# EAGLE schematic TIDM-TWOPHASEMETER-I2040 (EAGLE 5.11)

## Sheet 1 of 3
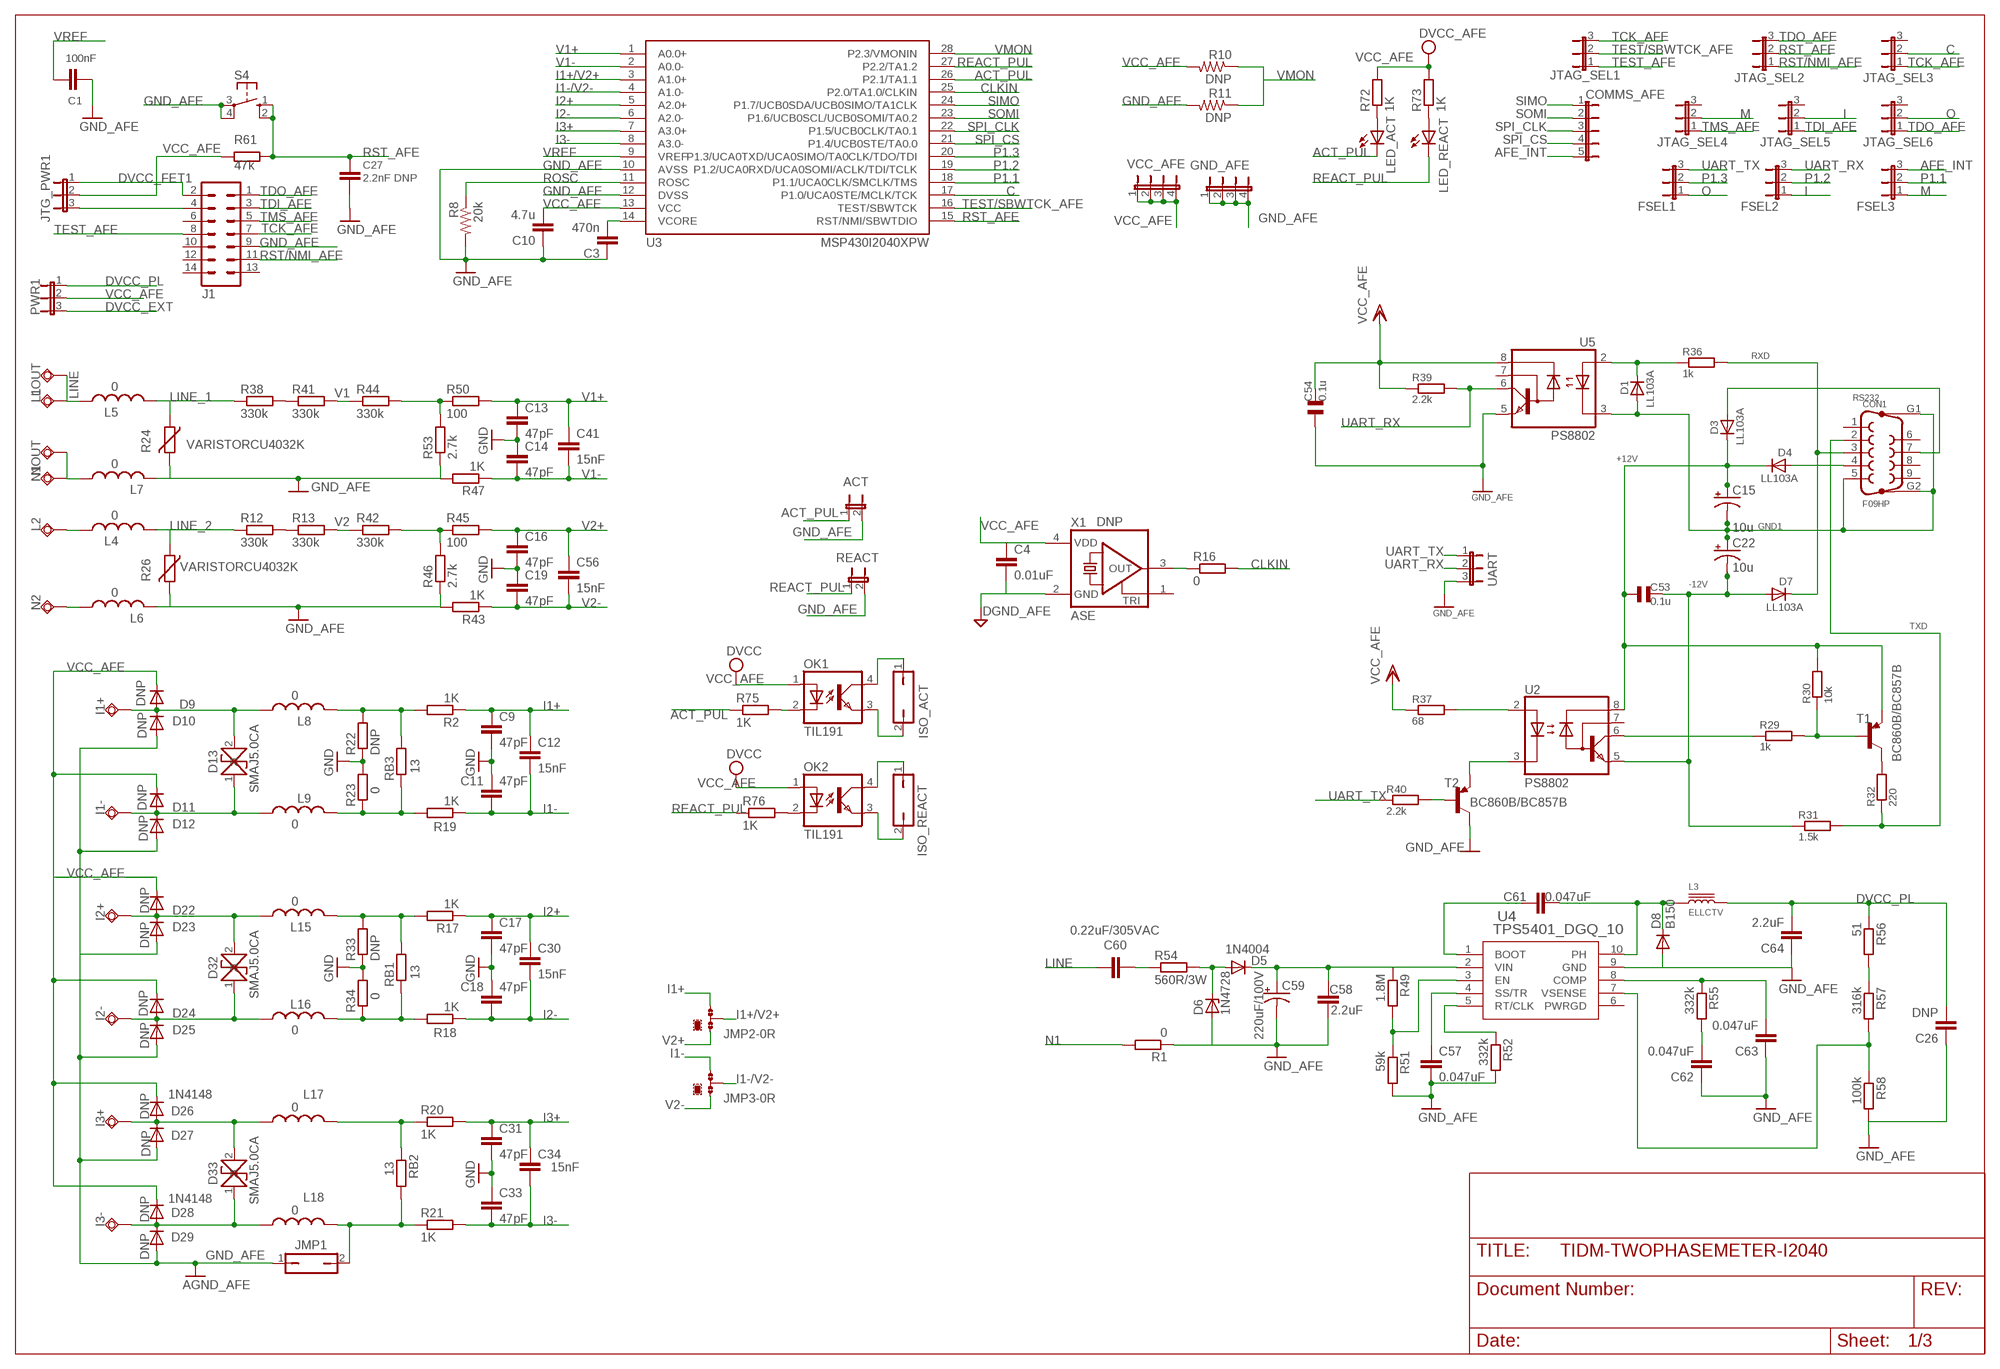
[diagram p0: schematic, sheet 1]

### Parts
ACT  JP1E  [JP1]
C1  100nF  C-EUC0603  [C0603]
C3  470n  C-EUC0603  [C0603]
C4  0.01uF  C-EUC0603  [C0603]
C9  47pF  C-EUC0603  [C0603]
C10  4.7u  C-EUC0603  [C0603]
C11  47pF  C-EUC0603  [C0603]
C12  15nF  C-EUC0603  [C0603]
C13  47pF  C-EUC0603  [C0603]
C14  47pF  C-EUC0603  [C0603]
C15  10u  CPOL-USCT3216  [CT3216]
C16  47pF  C-EUC0603  [C0603]
C17  47pF  C-EUC0603  [C0603]
C18  47pF  C-EUC0603  [C0603]
C19  47pF  C-EUC0603  [C0603]
C22  10u  CPOL-USCT3216  [CT3216]
C26  DNP  C-EUC0805  [C0805]
C27  2.2nF DNP  C-EUC0603  [C0603]
C30  15nF  C-EUC0603  [C0603]
C31  47pF  C-EUC0603  [C0603]
C33  47pF  C-EUC0603  [C0603]
C34  15nF  C-EUC0603  [C0603]
C41  15nF  C-EUC0603  [C0603]
C53  0.1u  CSMD0805  [CSMD0805]
C54  0.1u  CSMD0805  [CSMD0805]
C56  15nF  C-EUC0603  [C0603]
C57  0.047uF  C-EUC0603  [C0603]
C58  2.2uF  C-EUC1206  [C1206]
C59  220uF/100V  CPOL-USE5-13  [E5-13]
C60  0.22uF/305VAC  C15/8  [C15B8]
C61  0.047uF  C-EUC0603  [C0603]
C62  0.047uF  C-EUC0603  [C0603]
C63  0.047uF  C-EUC0603  [C0603]
C64  2.2uF  C-EUC0603  [C0603]
COMMS_AFE  JP5E  [JP5]
CON1  F09HP  [F09HP]
D1  LL103A  D  [SOD-80]
D3  LL103A  D  [SOD-80]
D4  LL103A  D  [SOD-80]
D5  1N4004  [DO41-10]
D6  1N4728  [DO41Z10]
D7  LL103A  D  [SOD-80]
D8  B150  DIODE-DO214BA  [DO214BA]
D9  1N4148  1N4148SOD80C  [SOD80C]
D10  1N4148  1N4148SOD80C  [SOD80C]
D11  1N4148  1N4148SOD80C  [SOD80C]
D12  1N4148  1N4148SOD80C  [SOD80C]
D13  SMAJ5.0CA  SMAJ  [DO-214]
D22  1N4148  1N4148SOD80C  [SOD80C]
D23  1N4148  1N4148SOD80C  [SOD80C]
D24  1N4148  1N4148SOD80C  [SOD80C]
D25  1N4148  1N4148SOD80C  [SOD80C]
D26  1N4148  1N4148SOD80C  [SOD80C]
D27  1N4148  1N4148SOD80C  [SOD80C]
D28  1N4148  1N4148SOD80C  [SOD80C]
D29  1N4148  1N4148SOD80C  [SOD80C]
D32  SMAJ5.0CA  SMAJ  [DO-214]
D33  SMAJ5.0CA  SMAJ  [DO-214]
FSEL1  HEADER0.05  JP2E  [JP2]
FSEL2  HEADER0.05  JP2E  [JP2]
FSEL3  HEADER0.05  JP2E  [JP2]
GND_AFE  JP4E  [JP4]
I1+  TPSQPAD1-20  [P1-20]
I1-  TPSQPAD1-20  [P1-20]
I2+  TPSQPAD1-20  [P1-20]
I2-  TPSQPAD1-20  [P1-20]
I3+  TPSQPAD1-20  [P1-20]
I3-  TPSQPAD1-20  [P1-20]
ISO_ACT  JP1Q  [JP1]
ISO_REACT  JP1Q  [JP1]
J1  ML14  [ML14]
JMP1  JP1Q  [JP1]
JMP2  0R-JUMPA  [A0R-JMP]
JMP3  0R-JUMPA  [A0R-JMP]
JTAG_SEL1  HEADER0.05  JP2E  [JP2]
JTAG_SEL2  HEADER0.05  JP2E  [JP2]
JTAG_SEL3  HEADER0.05  JP2E  [JP2]
JTAG_SEL4  HEADER0.05  JP2E  [JP2]
JTAG_SEL5  HEADER0.05  JP2E  [JP2]
JTAG_SEL6  HEADER0.05  JP2E  [JP2]
JTG_PWR1  JP2E  [JP2]
L1  TPSQPAD1-20  [P1-20]
L2  TPSQPAD1-20  [P1-20]
L3  ELLCTV  [ELLCTV]
L4  0  L-US08050805  [0805@1]
L5  0  L-US08050805  [0805@1]
L6  0  L-US08050805  [0805@1]
L7  0  L-US08050805  [0805@1]
L8  0  L-USL2012C  [L2012C]
L9  0  L-USL2012C  [L2012C]
L15  0  L-USL2012C  [L2012C]
L16  0  L-USL2012C  [L2012C]
L17  0  L-USL2012C  [L2012C]
L18  0  L-USL2012C  [L2012C]
LED_ACT  LED3MM  [LED3MM]
LED_REACT  LED3MM  [LED3MM]
LOUT  TPSQPAD1-20  [P1-20]
N1  TPSQPAD1-20  [P1-20]
N2  TPSQPAD1-20  [P1-20]
NOUT  TPSQPAD1-20  [P1-20]
OK1  TIL191  [DIL04]
OK2  TIL191  [DIL04]
PWR1  JP2E  [JP2]
R1  0  R-EU_R0805  [R0805]
R2  1K  R-EU_R0603  [R0603]
R8  20k  R-US_R0603  [R0603]
R10  DNP  R-US_R0603  [R0603]
R11  DNP  R-US_R0603  [R0603]
R12  330k  R-EU_R0603  [R0603]
R13  330k  R-EU_R0603  [R0603]
R16  0  R-EU_R0603  [R0603]
R17  1K  R-EU_R0603  [R0603]
R18  1K  R-EU_R0603  [R0603]
R19  1K  R-EU_R0603  [R0603]
R20  1K  R-EU_R0603  [R0603]
R21  1K  R-EU_R0603  [R0603]
R22  DNP  R-EU_R0603  [R0603]
R23  0  R-EU_R0603  [R0603]
R24  VARISTORCU4032K  [CU4032K]
R26  VARISTORCU4032K  [CU4032K]
R29  1k  R_0805  [0805]
R30  10k  R_0805  [0805]
R31  1.5k  R_0805  [0805]
R32  220  R_0805  [0805]
R33  DNP  R-EU_R0603  [R0603]
R34  0  R-EU_R0603  [R0603]
R36  1k  R_0805  [0805]
R37  68  R_0805  [0805]
R38  330k  R-EU_R0603  [R0603]
R39  2.2k  R_0805  [0805]
R40  2.2k  R_0805  [0805]
R41  330k  R-EU_R0603  [R0603]
R42  330k  R-EU_R0603  [R0603]
R43  1K  R-EU_R0603  [R0603]
R44  330k  R-EU_R0603  [R0603]
R45  100  R-EU_R0603  [R0603]
R46  2.7k  R-EU_R0603  [R0603]
R47  1K  R-EU_R0603  [R0603]
R49  1.8M  R-EU_R0603  [R0603]
R50  100  R-EU_R0603  [R0603]
R51  59k  R-EU_R0603  [R0603]
R52  332k  R-EU_R0603  [R0603]
R53  2.7k  R-EU_R0603  [R0603]
R54  560R/3W  R-EU_0414/5V  [0414V]
R55  332k  R-EU_R0603  [R0603]
R56  51  R-EU_R0603  [R0603]
R57  316k  R-EU_R0603  [R0603]
R58  100k  R-EU_R0603  [R0603]
R61  47k  R-EU_R0603  [R0603]
R72  1K  R-EU_R0603  [R0603]
R73  1K  R-EU_R0603  [R0603]
R75  1K  R-EU_R0603  [R0603]
R76  1K  R-EU_R0603  [R0603]
RB1  13  R-EU_R0603  [R0603]
RB2  13  R-EU_R0603  [R0603]
RB3  13  R-EU_R0603  [R0603]
REACT  JP1E  [JP1]
S4  10-XX  [B3F-10XX]
T1  BC860B/BC857B  BC857ASMD  [SOT23-BEC]
T2  BC860B/BC857B  BC857ASMD  [SOT23-BEC]
U2  PS8802  PS8802SO08  [SO08]
U3  MSP430I2040XPW  [TSSOP28]
U4  TPS5401_DGQ_10  [DGQ10_1P88X1P57]
U5  PS8802  PS8802SO08  [SO08]
UART  HEADER0.05  JP2E  [JP2]
VCC_AFE  JP4E  [JP4]
X1  ASE  [ASE]

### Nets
+12V: C15.+ C53.1 D3.2(K) D4.2(K) R30.2 T1.E U2.8(VCC)
+12V1: CON1.7 D3.1(A)
+12V3: CON1.4 D4.1(A)
-12V: C22.- C53.2 D7.1(A) R31.1 U2.5(GND)
ACT_PUL: ACT.1 LED_ACT.K(C) R75.1 U3.26(P2.1/TA1.1)
AFE_INT: COMMS_AFE.5 FSEL3.3 ; also sheet 2
C: JTAG_SEL3.2 U3.17(P1.0/UCA0STE/MCLK/TCK)
CLKIN: R16.2 U3.25(P2.0/TA1.0/CLKIN)
DVCC_EXT: PWR1.3
DVCC_FET1: J1.2 JTG_PWR1.1
DVCC_PL: C26.2 C64.2 L3.2 PWR1.1 R56.1
GND1: C15.- C22.+ CON1.5 CON1.G1 CON1.G2 D1.1(A) U5.3(C)
GND_AFE: ACT.2 C1.1 C3.1 C4.2 C9.2 C10.1 C11.1 C13.2 C14.1 C16.2 C17.2 C18.1 C19.1 C26.1 C27.2 C31.2 C33.1 C54.1 C57.2 C58.2 C59.- C62.1 C63.1 C64.1 D6.A D8.A D10.A D12.A D23.A D25.A D27.A D29.A GND_AFE.1 GND_AFE.2 GND_AFE.3 GND_AFE.4 J1.9 JMP1.1 L6.2 L7.2 R1.1 R8.2 R11.2 R22.1 R23.2 R24.2 R26.2 R33.1 R34.2 R43.2 R46.1 R47.2 R51.2 R52.2 R53.1 R58.2 REACT.2 S4.3(P) S4.4(P1) T2.C U3.10(AVSS) U3.12(DVSS) U4.9(GND) U5.5(GND) UART.3 X1.2(GND) ; supply symbol labelled GND, AGND_AFE, DGND_AFE ; also sheet 2
I: FSEL2.1 JTAG_SEL5.2
I1+: C9.1 C12.1 JMP2.1 R2.1
I1+/V2+: JMP2.2 U3.3(A1.0+)
I1-: C11.2 C12.2 JMP3.1 R19.1
I1-/V2-: JMP3.2 U3.4(A1.0-)
I2+: C17.1 C30.1 R17.1 U3.5(A2.0+)
I2-: C18.2 C30.2 R18.1 U3.6(A2.0-)
I3+: C31.1 C34.1 R20.2 U3.7(A3.0+)
I3-: C33.2 C34.2 R21.2 U3.8(A3.0-)
LINE: C60.1 L1.TP L5.1 LOUT.TP
LINE_1: L5.2 R24.1 R38.1
LINE_2: L4.2 R12.1 R26.1
M: FSEL3.1 JTAG_SEL4.2
N1: L7.1 N1.TP NOUT.TP R1.2
N$1: L2.TP L4.1
N$2: D1.2(K) R36.1 U5.2(A)
N$3: D9.A D10.C D13.2 I1+.TP L8.1
N$4: R29.1 U2.6(VO)
N$5: R32.2 T1.C
N$8: R40.2 T2.B
N$14: R52.1 U4.5(RT/CLK)
N$15: R12.2 R13.1
N$16: R42.2 R45.1 R46.2
N$17: C57.1 U4.4(SS/TR)
N$18: R49.2 R51.1 U4.3(EN)
N$19: D22.A D23.C D32.2 I2+.TP L15.1
N$20: D24.A D25.C D32.1 I2-.TP L16.1
N$21: D26.A D27.C D33.2 I3+.TP L17.1
N$22: D28.A D29.C D33.1 I3-.TP L18.1
N$23: R16.1 X1.3(OUT)
N$24: JMP1.2 L18.2 R21.1 RB2.2
N$25: C61.1 U4.1(BOOT)
N$26: D11.A D12.C D13.1 I1-.TP L9.1
N$27: L16.2 R18.2 R34.1 RB1.1
N$28: C58.1 C59.+ D5.C R49.1 U4.2(VIN)
N$29: L8.2 R2.2 R22.2 RB3.2
N$30: R29.2 R30.1 T1.B
N$31: L17.2 R20.1 RB2.1
N$32: R44.2 R50.1 R53.2
N$33: D5.A D6.C R54.2
N$34: C60.2 R54.1
N$35: C3.2 U3.14(VCORE)
N$36: C61.2 D8.C L3.1 U4.10(PH)
N$37: L9.2 R19.2 R23.1 RB3.1
N$39: R38.2 R41.1
N$40: R56.2 R57.1
N$41: R57.2 R58.1 U4.7(VSENSE)
N$42: L15.2 R17.2 R33.2 RB1.2
N$43: C63.2 R55.1 U4.8(COMP)
N$44: C62.2 R55.2
N$49: R37.2 U2.2(A)
N$104: LED_ACT.A R72.1
N$105: LED_REACT.A R73.1
N$109: ISO_ACT.1 OK1.4(COL)
N$113: OK2.2(C) R76.2
N$114: OK1.2(C) R75.2
N$117: ISO_ACT.2 OK1.3(EMIT)
N$118: ISO_REACT.1 OK2.4(COL)
N$119: ISO_REACT.2 OK2.3(EMIT)
N$130: J1.4 JTG_PWR1.3
N$455: T2.E U2.3(C)
NEUTRAL_1: L6.1 N2.TP
O: FSEL1.1 JTAG_SEL6.2
P1.1: FSEL3.2 U3.18(P1.1/UCA0CLK/SMCLK/TMS)
P1.2: FSEL2.2 U3.19(P1.2/UCA0RXD/UCA0SOMI/ACLK/TDI/TCLK)
P1.3: FSEL1.2 U3.20(P1.3/UCA0TXD/UCA0SIMO/TA0CLK/TDO/TDI)
REACT_PUL: LED_REACT.K(C) R76.1 REACT.1 U3.27(P2.2/TA1.2)
ROSC: R8.1 U3.11(ROSC)
RST/NMI_AFE: J1.11 JTAG_SEL2.1
RST_AFE: C27.1 JTAG_SEL2.2 R61.2 S4.1(S) S4.2(S1) U3.15(RST/NMI/SBWTDIO)
RXD: CON1.3 D7.2(K) R36.2
SIMO: COMMS_AFE.1 U3.24(P1.7/UCB0SDA/UCB0SIMO/TA1CLK) ; also sheet 2
SOMI: COMMS_AFE.2 U3.23(P1.6/UCB0SCL/UCB0SOMI/TA0.2) ; also sheet 2
SPI_CLK: COMMS_AFE.3 U3.22(P1.5/UCB0CLK/TA0.1) ; also sheet 2
SPI_CS: COMMS_AFE.4 U3.21(P1.4/UCB0STE/TA0.0) ; also sheet 2
TCK_AFE: J1.7 JTAG_SEL1.3 JTAG_SEL3.1
TDI_AFE: J1.3 JTAG_SEL5.1
TDO_AFE: J1.1 JTAG_SEL2.3 JTAG_SEL6.1
TEST/SBWTCK_AFE: JTAG_SEL1.2 U3.16(TEST/SBWTCK)
TEST_AFE: J1.8 JTAG_SEL1.1
TMS_AFE: J1.5 JTAG_SEL4.1
TXD: CON1.2 R31.2 R32.1
UART_RX: FSEL2.3 R39.2 U5.6(VO) UART.2
UART_TX: FSEL1.3 R40.1 UART.1
V1: R41.2 R44.1
V1+: C13.1 C41.1 R50.2 U3.1(A0.0+)
V1-: C14.2 C41.2 R47.1 U3.2(A0.0-)
V2: R13.2 R42.1
V2+: C16.1 C56.1 JMP2.3 R45.2
V2-: C19.2 C56.2 JMP3.3 R43.1
VCC_AFE: C4.1 C10.2 C54.2 D9.C D11.C D22.C D24.C D26.C D28.C JTG_PWR1.2 OK1.1(A) OK2.1(A) PWR1.2 R10.2 R37.1 R39.1 R61.1 R72.2 R73.2 U3.13(VCC) U5.8(VCC) VCC_AFE.1 VCC_AFE.2 VCC_AFE.3 VCC_AFE.4 X1.4(VDD) ; supply symbol labelled DVCC_AFE, DVCC ; also sheet 2
VMON: R10.1 R11.1 U3.28(P2.3/VMONIN)
VREF: C1.2 U3.9(VREF)
Unconnected: CON1.1 CON1.6 CON1.8 CON1.9 J1.6 J1.10 J1.12 J1.13 J1.14 JTAG_SEL3.3 JTAG_SEL4.3 JTAG_SEL5.3 JTAG_SEL6.3 U2.7(VB) U4.6(PWRGD) U5.7(VB) X1.1(TRI)

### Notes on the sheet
- RS232
- DNP
- DNP
- DNP
- DNP
- DNP
- DNP
- DNP
- DNP
- DNP
- DNP
- DNP
- DNP
- DNP

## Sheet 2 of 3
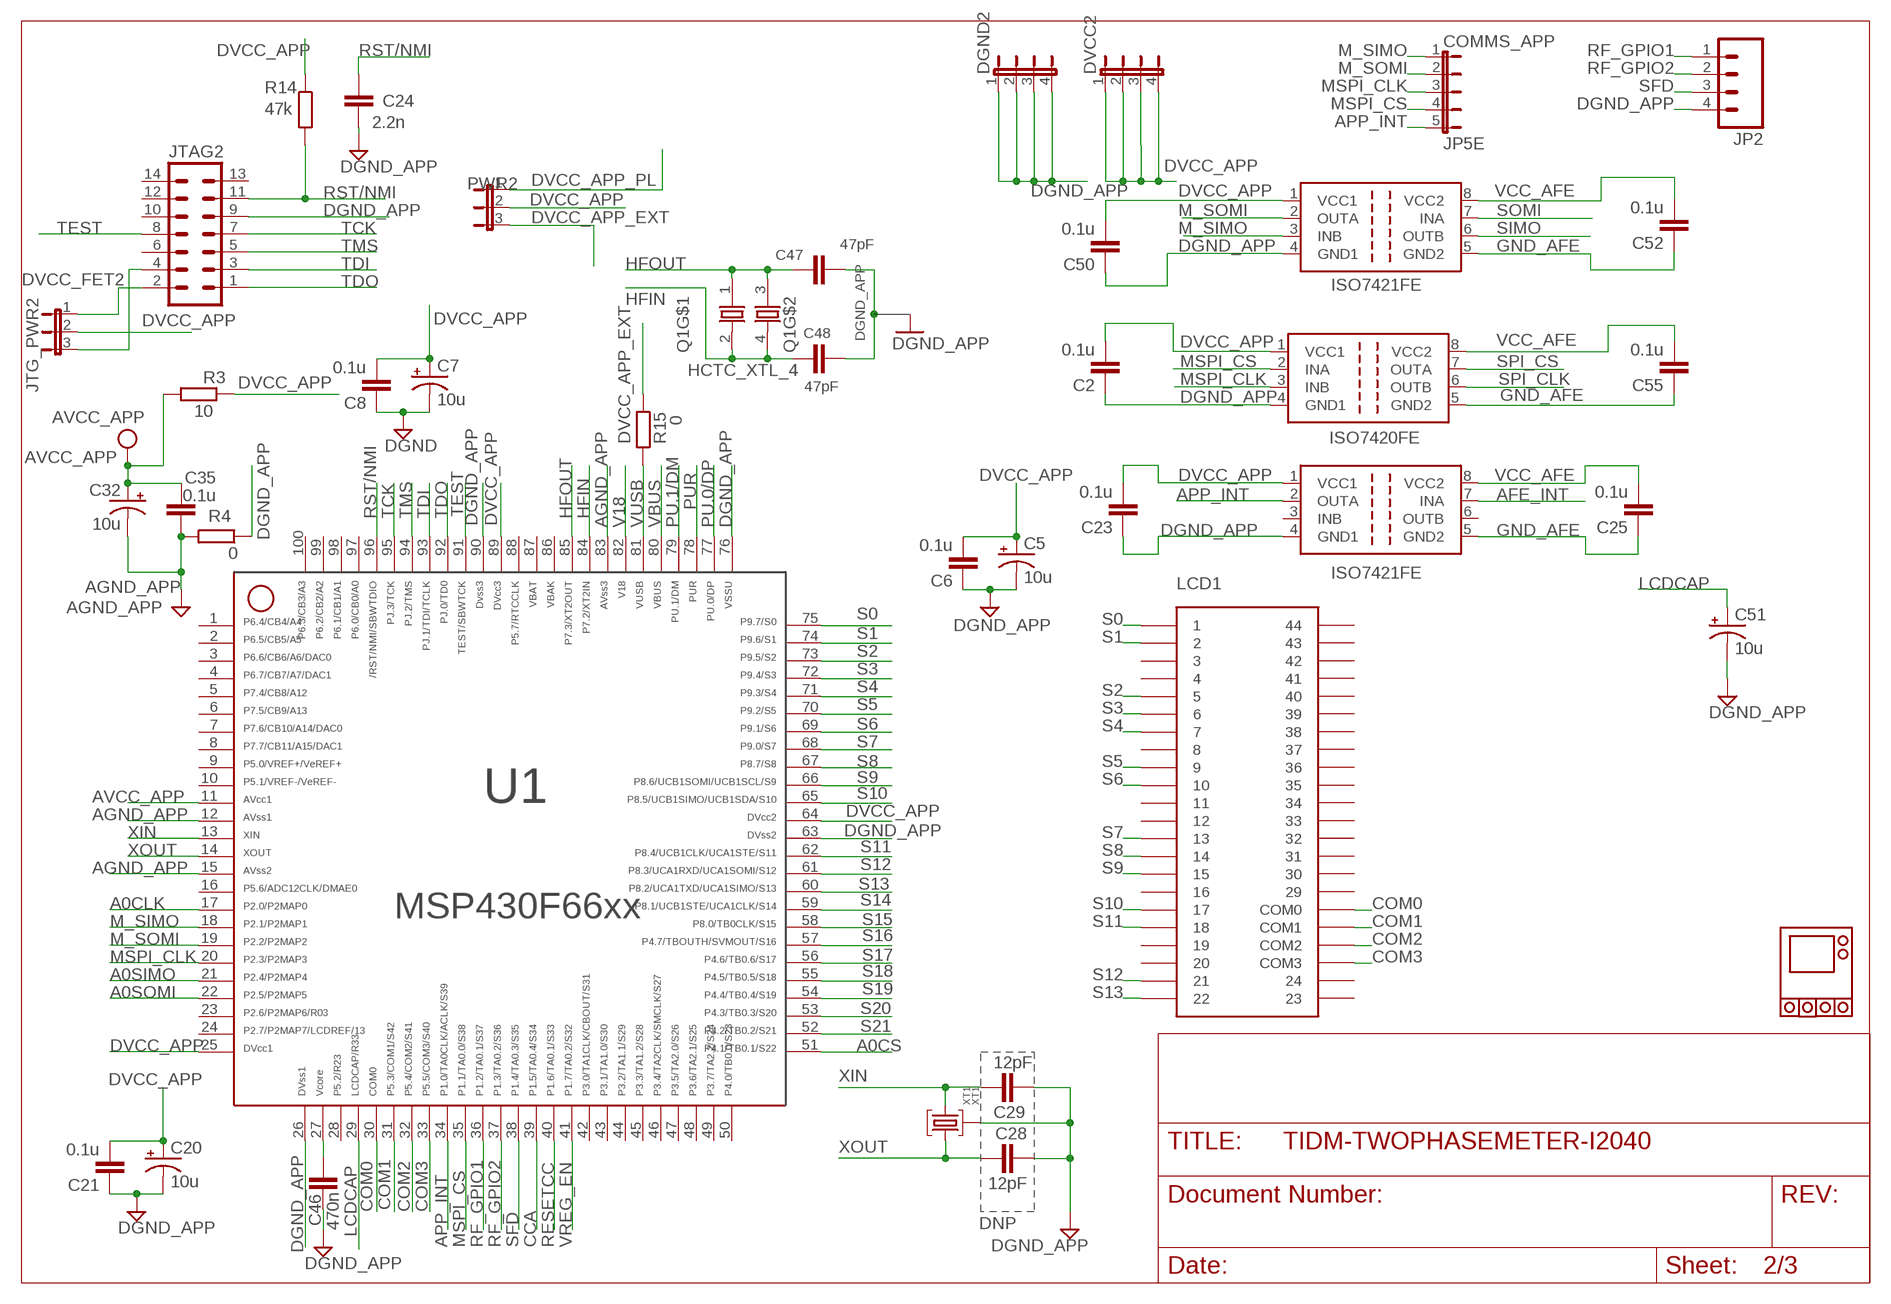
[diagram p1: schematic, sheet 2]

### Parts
C2  0.1u  C-EUC0603  [C0603]
C5  10u  CPOL-USCT3216  [CT3216]
C6  0.1u  C-EUC0603  [C0603]
C7  10u  CPOL-USCT3216  [CT3216]
C8  0.1u  C-EUC0603  [C0603]
C20  10u  CPOL-USCT3216  [CT3216]
C21  0.1u  C-EUC0603  [C0603]
C23  0.1u  C-EUC0603  [C0603]
C24  2.2n  C-EUC0603  [C0603]
C25  0.1u  C-EUC0603  [C0603]
C28  12pF  C-EUC0603  [C0603]
C29  12pF  C-EUC0603  [C0603]
C32  10u  CPOL-USCT3216  [CT3216]
C35  0.1u  C-EUC0603  [C0603]
C46  470n  C-EUC0603  [C0603]
C47  47pF  C-EUC0603  [C0603]
C48  47pF  C-EUC0603  [C0603]
C50  0.1u  C-EUC0603  [C0603]
C51  10u  CPOL-USCT3216  [CT3216]
C52  0.1u  C-EUC0603  [C0603]
C55  0.1u  C-EUC0603  [C0603]
CASE1  3_PHASE_CASE  [3_PHASE_CASE]
COMMS_APP  JP5E  [JP5]
DGND2  JP4E  [JP4]
DVCC2  JP4E  [JP4]
ISO1  ISO7420FE  ISO7220A  [SO-08]
ISO2  ISO7421FE  ISO7221A  [SO-08]
ISO3  ISO7421FE  ISO7221A  [SO-08]
JP2  M04SMD  [1X04-SMD]
JTAG2  ML14  [ML14]
JTG_PWR2  JP2E  [JP2]
LCD1  TI_160SEG_LCD  [TI_160SEG_LCD]
PWR2  JP2E  [JP2]
Q1  HCTC_XTL_4  [HCTC]
R3  10  R-EU_R0603  [R0603]
R4  0  R-EU_R0603  [R0603]
R14  47k  R-EU_R0603  [R0603]
R15  0  R-EU_R0603  [R0603]
U1  F66XX---PZ100  [PZ100]
XT1  XT1  CM200T  [CM200T]

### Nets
A0CLK: U1.17 ; also sheet 3
A0CS: U1.51 ; also sheet 3
A0SIMO: U1.21 ; also sheet 3
A0SOMI: U1.22 ; also sheet 3
AFE_INT: ISO3.7(INA) ; also sheet 1
AGND_APP: C32.- C35.1 R4.2 U1.12 U1.15 U1.83
APP_INT: COMMS_APP.5 ISO3.2(OUTA) U1.34
AVCC_APP: C32.+ C35.2 R3.2 U1.11
CCA: U1.39 ; also sheet 3
COM0: LCD1.COM0 U1.30
COM1: LCD1.COM1 U1.31
COM2: LCD1.COM2 U1.32
COM3: LCD1.COM3 U1.33
DGND_APP: C2.1 C5.- C6.1 C7.- C8.1 C20.- C21.1 C23.1 C24.1 C28.1 C29.2 C46.2 C47.2 C48.2 C50.1 C51.- DGND2.1 DGND2.2 DGND2.3 DGND2.4 ISO1.4(GND1) ISO2.4(GND1) ISO3.4(GND1) JP2.4 JTAG2.9 R4.1 U1.26 U1.63 U1.76 U1.90 XT1.P3 ; supply symbol labelled DGND ; also sheet 3
DVCC_APP: C2.2 C5.+ C6.2 C7.+ C8.2 C20.+ C21.2 C23.2 C50.2 DVCC2.1 DVCC2.2 DVCC2.3 DVCC2.4 ISO1.1(VCC1) ISO2.1(VCC1) ISO3.1(VCC1) JTG_PWR2.2 PWR2.2 R3.1 R14.1 U1.25 U1.64 U1.89 ; also sheet 3
DVCC_APP_EXT: PWR2.3 R15.1
DVCC_APP_PL: PWR2.1 ; also sheet 3
DVCC_FET2: JTAG2.2 JTG_PWR2.1
GND_AFE: C25.1 C52.1 C55.1 ISO1.5(GND2) ISO2.5(GND2) ISO3.5(GND2) ; also sheet 1
HFIN: C48.1 Q1.2 Q1.4 U1.84
HFOUT: C47.1 Q1.1 Q1.3 U1.85
LCDCAP: C51.+ U1.29
M_SIMO: COMMS_APP.1 ISO2.3(INB) U1.18
M_SOMI: COMMS_APP.2 ISO2.2(OUTA) U1.19
MSPI_CLK: COMMS_APP.3 ISO1.3(INB) U1.20
MSPI_CS: COMMS_APP.4 ISO1.2(INA) U1.35
N$9: JTAG2.4 JTG_PWR2.3
N$11: C46.1 U1.27
PU.0/DP: U1.77 ; also sheet 3
PU.1/DM: U1.79 ; also sheet 3
PUR: U1.78 ; also sheet 3
RESETCC: U1.40 ; also sheet 3
RF_GPIO1: JP2.1 U1.36 ; also sheet 3
RF_GPIO2: JP2.2 U1.37 ; also sheet 3
RST/NMI: C24.2 JTAG2.11 R14.2 U1.96
S0: LCD1.1 U1.75
S1: LCD1.2 U1.74
S2: LCD1.5 U1.73
S3: LCD1.6 U1.72
S4: LCD1.7 U1.71
S5: LCD1.9 U1.70
S6: LCD1.10 U1.69
S7: LCD1.13 U1.68
S8: LCD1.14 U1.67
S9: LCD1.15 U1.66
S10: LCD1.17 U1.65
S11: LCD1.18 U1.62
S12: LCD1.21 U1.61
S13: LCD1.22 U1.60
S14: U1.59
S15: U1.58
S16: U1.57
S17: U1.56
S18: U1.55
S19: U1.54
S20: U1.53
S21: U1.52
SFD: JP2.3 U1.38 ; also sheet 3
SIMO: ISO2.6(OUTB) ; also sheet 1
SOMI: ISO2.7(INA) ; also sheet 1
SPI_CLK: ISO1.6(OUTB) ; also sheet 1
SPI_CS: ISO1.7(OUTA) ; also sheet 1
TCK: JTAG2.7 U1.95
TDI: JTAG2.3 U1.93
TDO: JTAG2.1 U1.92
TEST: JTAG2.8 U1.91
TMS: JTAG2.5 U1.94
V18: U1.82
VBUS: U1.80 ; also sheet 3
VCC_AFE: C25.2 C52.2 C55.2 ISO1.8(VCC2) ISO2.8(VCC2) ISO3.8(VCC2) ; also sheet 1
VREG_EN: U1.41 ; also sheet 3
VUSB: R15.2 U1.81
XIN: C29.1 U1.13 XT1.P2
XOUT: C28.2 U1.14 XT1.P1
Unconnected: ISO3.3(INB) ISO3.6(OUTB) JTAG2.6 JTAG2.10 JTAG2.12 JTAG2.13 JTAG2.14 LCD1.3 LCD1.4 LCD1.8 LCD1.11 LCD1.12 LCD1.16 LCD1.19 LCD1.20 LCD1.23 LCD1.24 LCD1.29 LCD1.30 LCD1.31 LCD1.32 LCD1.33 LCD1.34 LCD1.35 LCD1.36 LCD1.37 LCD1.38 LCD1.39 LCD1.40 LCD1.41 LCD1.42 LCD1.43 LCD1.44 U1.1 U1.2 U1.3 U1.4 U1.5 U1.6 U1.7 U1.8 U1.9 U1.10 U1.16 U1.23 U1.24 U1.28 U1.42 U1.43 U1.44 U1.45 U1.46 U1.47 U1.48 U1.49 U1.50 U1.86 U1.87 U1.88 U1.97 U1.98 U1.99 U1.100

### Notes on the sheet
- ISO7421FE
- ISO7420FE
- ISO7421FE
- DNP

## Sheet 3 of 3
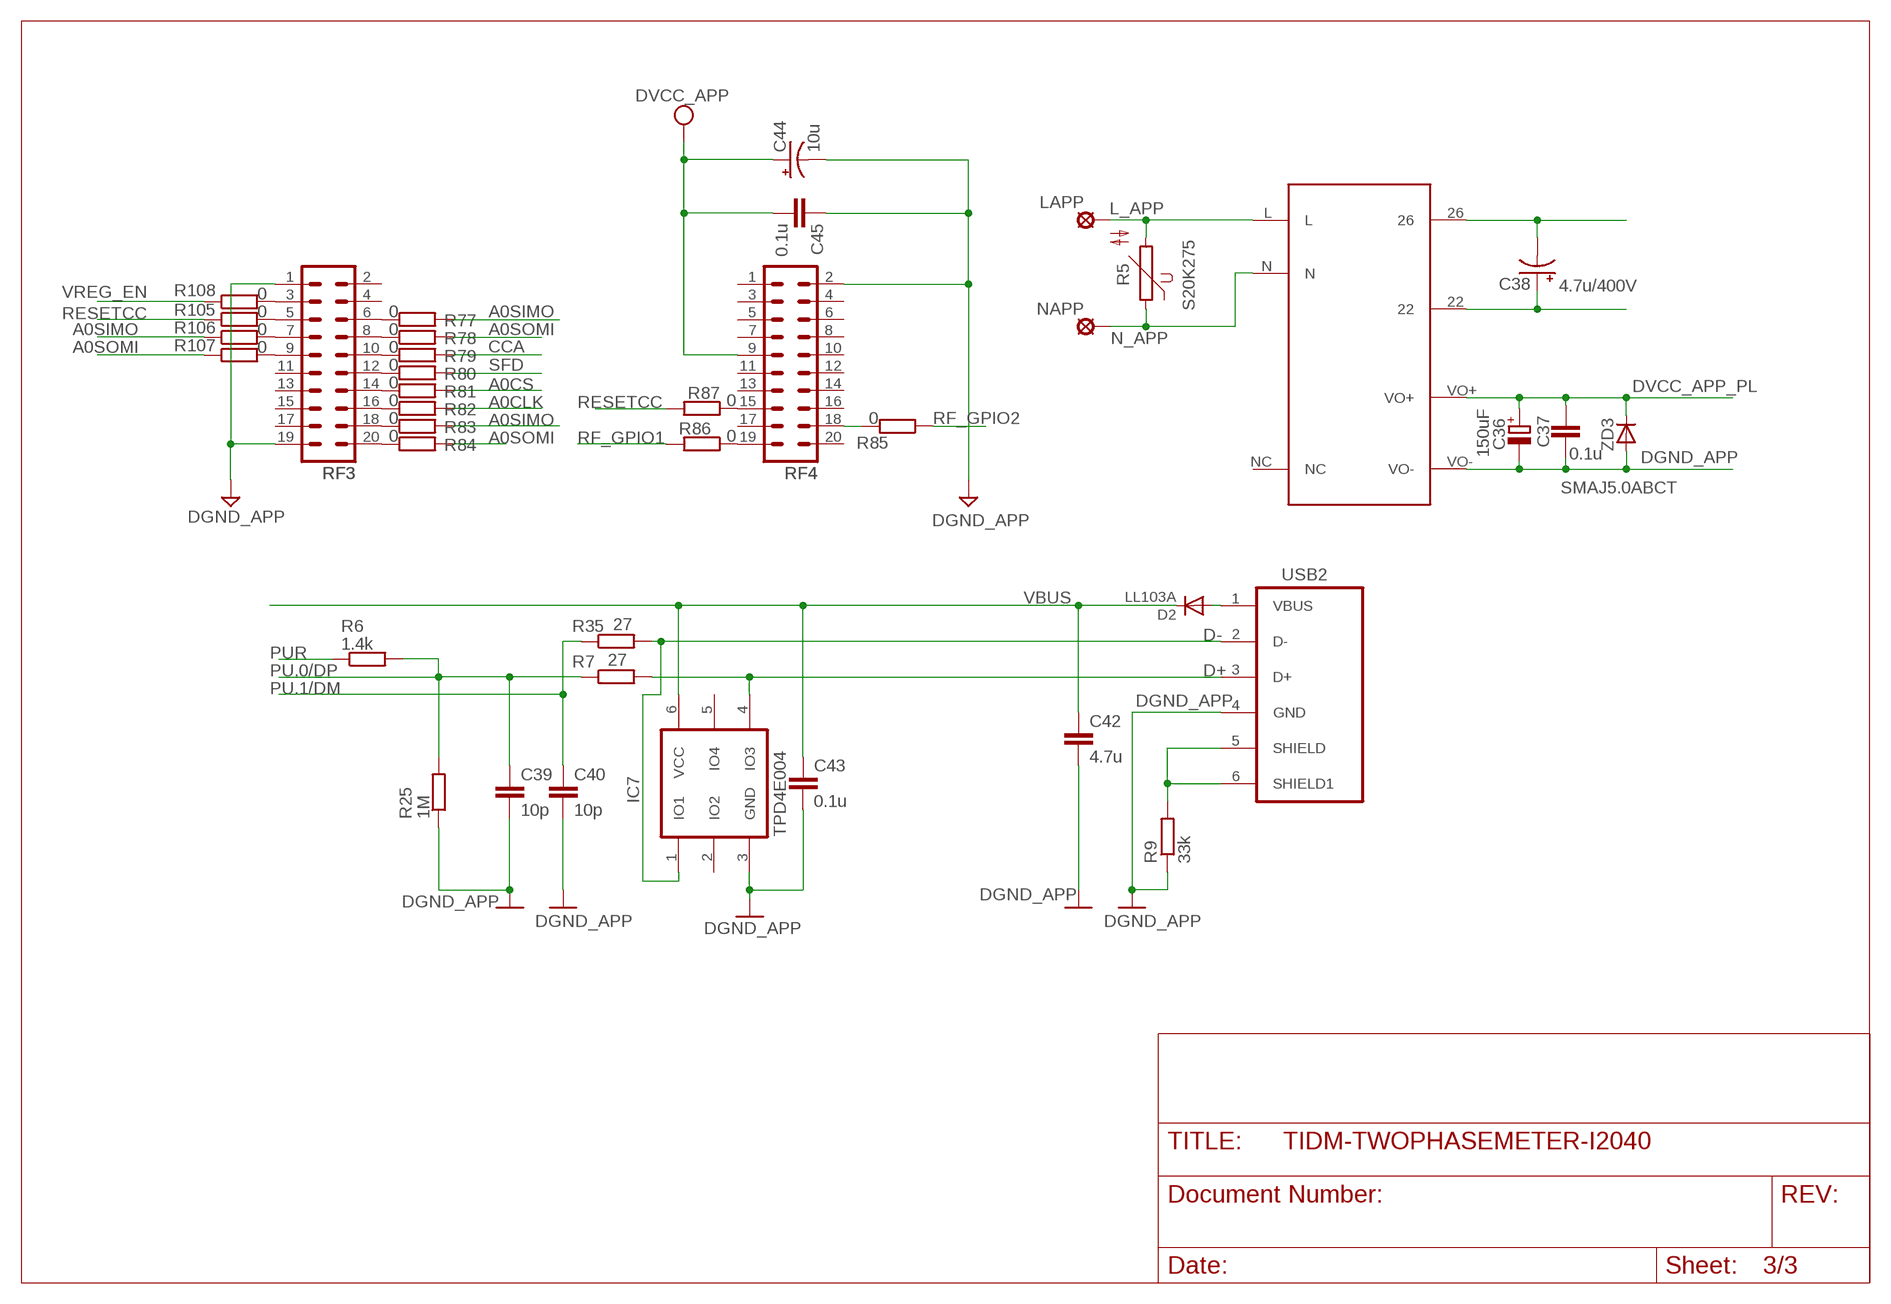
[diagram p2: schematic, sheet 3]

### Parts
C36  150uF  CPOL-EUE2-5  [E2-5]
C37  0.1u  C-EUC0603  [C0603]
C38  4.7u/400V  CPOL-USE5-10.5  [E5-10,5]
C39  10p  C-EUC0603  [C0603]
C40  10p  C-EUC0603  [C0603]
C42  4.7u  C-EUC0603  [C0603]
C43  0.1u  C-EUC0603  [C0603]
C44  10u  CPOL-USCT3216  [CT3216]
C45  0.1u  C-EUC0603  [C0603]
D2  LL103A  D  [SOD-80]
IC7  TPD4E004  [DRY6]
LAPP  LSP10  [LSP10]
NAPP  LSP10  [LSP10]
R5  S20K275  [S20K275]
R6  1.4k  R-EU_R0603  [R0603]
R7  27  R-EU_R0603  [R0603]
R9  33k  R-EU_R0603  [R0603]
R25  1M  R-EU_R0603  [R0603]
R35  27  R-EU_R0603  [R0603]
R77  0  R-EU_R0603  [R0603]
R78  0  R-EU_R0603  [R0603]
R79  0  R-EU_R0603  [R0603]
R80  0  R-EU_R0603  [R0603]
R81  0  R-EU_R0603  [R0603]
R82  0  R-EU_R0603  [R0603]
R83  0  R-EU_R0603  [R0603]
R84  0  R-EU_R0603  [R0603]
R85  0  R-EU_R0603  [R0603]
R86  0  R-EU_R0603  [R0603]
R87  0  R-EU_R0603  [R0603]
R105  0  R-EU_R0603  [R0603]
R106  0  R-EU_R0603  [R0603]
R107  0  R-EU_R0603  [R0603]
R108  0  R-EU_R0603  [R0603]
RF3  TFM-110-02-SM-D-A-K  [TFM-110-02-SM-D-A-K]
RF4  TFM-110-02-SM-D-A-K  [TFM-110-02-SM-D-A-K]
U$2  CUI_XR  [CUI_XR]
USB2  USB_RECEPTACLE  [USB_BUCHSE]
ZD3  SMAJ5.0ABCT  DIODE-DO214AC  [DO214AC]

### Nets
A0CLK: R82.2 ; also sheet 2
A0CS: R81.2 ; also sheet 2
A0SIMO: R77.2 R83.2 R106.1 ; also sheet 2
A0SOMI: R78.2 R84.2 R107.1 ; also sheet 2
CCA: R79.2 ; also sheet 2
D+: IC7.4(IO3) R7.2 USB2.3(D+)
D-: IC7.1(IO1) R35.2 USB2.2(D-)
DGND_APP: C36.- C37.2 C39.2 C40.2 C42.2 C43.2 C44.- C45.1 IC7.3(GND) R9.1 R25.1 RF3.1 RF3.19 RF4.2 U$2.VO- USB2.4(GND) ZD3.A ; also sheet 2
DVCC_APP: C44.+ C45.2 RF4.9 ; also sheet 2
DVCC_APP_PL: C36.+ C37.1 U$2.VO+ ZD3.C ; also sheet 2
L_APP: LAPP.MP R5.2 U$2.L
N$6: R107.2 RF3.9
N$7: R87.1 RF4.15
N$10: R9.2 USB2.5(SHIELD) USB2.6(SHIELD1)
N$12: C38.- U$2.26
N$13: C38.+ U$2.22
N$51: D2.1(A) USB2.1(VBUS)
N$52: R108.2 RF3.3
N$56: R77.1 RF3.6
N$57: R78.1 RF3.8
N$58: R79.1 RF3.10
N$60: R80.1 RF3.12
N$61: R81.1 RF3.14
N$62: R82.1 RF3.16
N$63: R83.1 RF3.18
N$64: R84.1 RF3.20
N$65: R85.2 RF4.18
N$108: R86.1 RF4.19
N$110: R105.2 RF3.5
N$111: R106.2 RF3.7
N_APP: NAPP.MP R5.1 U$2.N
PU.0/DP: C39.1 R6.2 R7.1 R25.2 ; also sheet 2
PU.1/DM: C40.1 R35.1 ; also sheet 2
PUR: R6.1 ; also sheet 2
RESETCC: R87.2 R105.1 ; also sheet 2
RF_GPIO1: R86.2 ; also sheet 2
RF_GPIO2: R85.1 ; also sheet 2
SFD: R80.2 ; also sheet 2
VBUS: C42.1 C43.1 D2.2(K) IC7.6(VCC) ; also sheet 2
VREG_EN: R108.1 ; also sheet 2
Unconnected: IC7.2(IO2) RF3.2 RF3.4 RF3.11 RF3.13 RF3.15 RF3.17 RF4.1 RF4.3 RF4.4 RF4.5 RF4.6 RF4.7 RF4.8 RF4.10 RF4.11 RF4.12 RF4.13 RF4.14 RF4.16 RF4.17 RF4.20 U$2.NC

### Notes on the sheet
- 0
- 0 | 0
- 0 | 0
- 0 | 0
- 0
- 0
- 0 | 0
- 0 | 0
- 0 | 0

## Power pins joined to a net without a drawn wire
IO4: IC7.5(IO4)

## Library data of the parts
ACT REACT = jumper:JP1E: JUMPER
C1-C4 C6 C8 C10 C14 C16 C19 C21 C23-C25 C27-C29 C35 C37 C39-C43 C45-C48 C50 C52 C55 C56 = resistor:C-EU: CAPACITOR, European symbol
C5 C7 C15 C20 C22 C32 C38 C44 C51 = rcl:CPOL-US: POLARIZED CAPACITOR, American symbol
C9 C11-C13 C17 C18 C26 C30 C31 C33 C34 C57 C58 C61-C64 = rcl:C-EU: CAPACITOR, European symbol
C36 = rcl:CPOL-EU: POLARIZED CAPACITOR, European symbol
C53 C54 = CAP:CSMD0805
C59 = resistor:CPOL-US: POLARIZED CAPACITOR, American symbol
C60 = capacitor-wima:C: CAPACITOR
CASE1 = meter_cases:3_PHASE_CASE
COMMS_AFE COMMS_APP = jumper:JP5E
CON1 = SUBD-A:F09HP
D1-D4 D7 = SMD:D
D5 = diode:1N4004: DIODE
D6 = diode:1N4728: Z DIODE
D8 ZD3 = diode:DIODE-: DIODE
D9-D12 D22-D29 = ElecMeter:1N4148: DIODE
D13 D32 D33 = CON1:SMAJ
DGND2 DVCC2 GND_AFE VCC_AFE = jumper:JP4E: JUMPER
FSEL1-FSEL3 JTAG_SEL1-JTAG_SEL6 JTG_PWR1 JTG_PWR2 PWR1 PWR2 UART = jumper:JP2E: JUMPER
I1+ I1- I2+ I2- I3+ I3- L1 L2 LOUT N1 N2 NOUT = testpad:TPSQ: Test pad
IC7 = gangprog:TPD4E004
ISO1 = texas:ISO7220: DUAL DIGITAL ISOLATORS Source: http://focus.ti.com/lit/ds/symlink/iso7221a.pdf; MPN: ISO7220AD; OC_FARNELL: 1390649; OC_NEWARK: 48M0666
ISO2 ISO3 = texas:ISO7221: DUAL DIGITAL ISOLATORS Source: http://focus.ti.com/lit/ds/symlink/iso7221a.pdf; MPN: ISO7221AD; OC_FARNELL: 1390651; OC_NEWARK: 48M0672
ISO_ACT ISO_REACT JMP1 = ElecMeter:JP1Q: JUMPER
J1 JTAG2 = CON-ML:ML14: HARTING; OC_FARNELL: unknown; OC_NEWARK: unknown
JMP2 JMP3 = jump-0r-smd:0R-JUMP: SMD 0R 0805 Jumper
JP2 = SparkFun:M04: Header 4 Standard 4-pin 0.1" header. Use with straight break away headers (SKU : PRT-00116), right angle break away headers (PRT-00553), swiss pins (PRT-00743), machine pins (PRT-00117), and female headers (PRT-00115). Molex polarized connector foot print use with SKU : PRT-08231 with associated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
L3 = ELLCTV:ELLCTV
L4-L7 = SMD:L-US0805
L8 L9 L15-L18 = ElecMeter:L-US: INDUCTOR, American symbol
LAPP NAPP = ElecMeter:LSP10: SOLDER PAD
LCD1 = Personal:TI_160SEG_LCD
LED_ACT LED_REACT = ElecMeter:LED: LED
OK1 OK2 = ElecMeter:TIL191: TEXAS INSTRUMENTS OPTO COUPLER
Q1 = scrystal:HCTC_XTL_4
R1-R4 R6 R7 R9 R12-R23 R25 R33-R35 R38 R41-R47 R49-R53 R55-R58 R61 RB1-RB3 = resistor:R-EU_: RESISTOR, European symbol
R5 = varistor:S20K275: VARISTOR
R8 R10 R11 = resistor:R-US_: RESISTOR, American symbol
R24 R26 = varistor:VARISTOR: VARISTOR
R29-R32 R36 R37 R39 R40 = SMD:R_0805
R54 R72 R73 R75-R87 R105-R108 = rcl:R-EU_: RESISTOR, European symbol
RF3 RF4 = _MSP430:TFM-110-02-SM-D-A-K
S4 = ElecMeter:10-XX: OMRON SWITCH
T1 T2 = transistor-pnp:BC857*: PNP Transistror
U1 = TI_MSP430_v16_intern:F66XX---PZ100: ***MSP430F66XX***PZ64 Rev 1.0 *** 06/2010
U2 U5 = FE449x EVM:PS8802: MOTOROLA OPTO COUPLER
U3 = MSP430i204x:MSP430I2040XPW
U4 = TPS5401_DGQ_10:TPS5401_DGQ_10; DATASHEETURL: http://www.ti.com/lit/gpn/TPS5401; DESCRIPTION: 3.5V to 42V Input, 0.5 A Step Down Converter; FAMILY_NAME: STEP-DOWN REGULATOR; GENERIC_PART_NUMBER: TPS5401; INDUSTRY_STD_PKG_TYPE: MSOP-PowerPAD; MANUFACTURER: Texas Instruments; MANUFACTURER_PART_NUMBER: tps5401_dgq_10; PACKAGE_DESIGNATOR: DGQ; PIN_COUNT: 10; VENDOR: Texas Instruments
U$2 = TI_MSP430_v16_intern:CUI_XR
USB2 = susbfet:USB_RECEPTACLE: Lumberg: USB-Receptacle "B", 2413
X1 = crystal:ASE: 3.3Vdc CMOS SMD CRYSTAL CLOCK OSCILLATOR SOurce: www.abracon.com; OC_FARNELL: unknown; OC_NEWARK: unknown
XT1 = F20xx PIR Demo & Eval:CM200T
